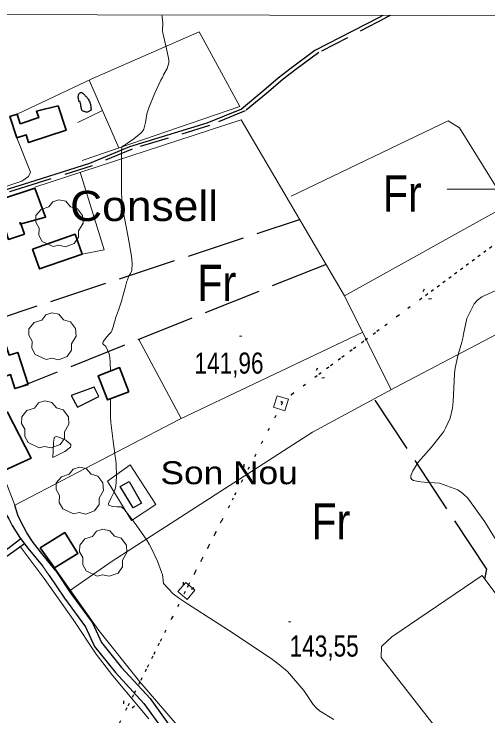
# Model space of a CAD drawing. Extents: x 483855 to 488461, y 4388206 to 4391419.
# Drawn here: x 484295.6 to 484491.9, y 4390781.6 to 4391072.6 of the extents above; entities that cross this region are included whole.
import ezdxf
from ezdxf.enums import TextEntityAlignment as Align

# ---------------------------------------------------------------- set-up
doc = ezdxf.new("R2010")
doc.units = 0
doc.header["$LTSCALE"] = 4
for name, pattern in [('DOTTED', [1.5, 0.3, -1.2]), ('LONG_DASHED', [7.5, 6, -1.5]), ('MEDIUM_DASHED', [4.5, 3, -1.5])]:
    doc.linetypes.add(name, pattern=pattern)
for name, color, linetype, lineweight in [('1', 7, 'Continuous', 13), ('21', 7, 'Continuous', 25), ('25', 7, 'LONG_DASHED', 25), ('29', 7, 'Continuous', 13), ('36', 7, 'Continuous', 25), ('38', 7, 'Continuous', 25), ('43', 7, 'DOTTED', 25), ('47', 7, 'Continuous', 35), ('51', 7, 'Continuous', 13), ('7', 7, 'Continuous', 13), ('9', 7, 'Continuous', 13)]:
    doc.layers.add(name, color=color, linetype=linetype, lineweight=lineweight)
doc.layers.add('31', color=7, linetype='Continuous')
doc.layers.add('5', color=7, linetype='Continuous')

msp = doc.modelspace()

# ---------------------------------------------------------------- linework, layer by layer
at = {"layer": '1'}
msp.add_line((484475, 4391000), (484525, 4391000), dxfattribs=at)
msp.add_lwpolyline([(484115.5, 4391072.6), (487689.7, 4391065.7), (487685.8, 4388753.5), (484110.5, 4388760.3)], close=True, dxfattribs=at)
at = {"layer": '21'}
for points in [[(484328.8, 4390917.84), (484319.29, 4390914.38), (484321.9, 4390909.66), (484330.8, 4390913.99)], [(484343.25, 4390878.75), (484348.42, 4390869.82), (484344.96, 4390867.88), (484339.52, 4390876.75)]]:
    msp.add_lwpolyline(points, close=True, dxfattribs=at)
msp.add_spline([(484322.66, 4391036.12), (484322.26, 4391037.5), (484322.23, 4391038.35), (484322.32, 4391038.99), (484323, 4391039.94), (484323.27, 4391040), (484323.85, 4391039.97), (484324.17, 4391039.77), (484324.66, 4391039.16), (484325.61, 4391038.28), (484326.28, 4391037.34), (484326.77, 4391036.47), (484327.12, 4391035.48), (484327.39, 4391034.11), (484327.39, 4391034.04), (484327.4, 4391032.68), (484327.33, 4391032.61), (484327.26, 4391032.55), (484326.53, 4391032.12), (484326, 4391031.95), (484325.42, 4391031.91), (484324.77, 4391032.13), (484324.2, 4391032.35), (484323.76, 4391032.69), (484323.58, 4391033.15), (484323.46, 4391033.55), (484323.36, 4391034.07), (484323.26, 4391035.05), (484323.04, 4391035.97), (484322.87, 4391036.5)], degree=3, dxfattribs=at)
at = {"layer": '25'}
for p, q in [((484282.36, 4390944.05), (484413.92, 4390987.45)), ((484424.89, 4390968.79), (484299.04, 4390918.32))]:
    msp.add_line(p, q, dxfattribs=at)
msp.add_lwpolyline([(484490.58, 4390838.33), (484491.44, 4390842.4), (484444.89, 4390913.1)], dxfattribs=at)
at = {"layer": '29'}
for points in [[(484311.84, 4390976.2), (484307.3, 4390978.32), (484305.89, 4390980.86), (484305.99, 4390983.84), (484304.62, 4390986.25), (484304.66, 4390989), (484306.82, 4390991.6), (484310.01, 4390992.6), (484311.66, 4390994.79), (484314.23, 4390995.62), (484317.09, 4390994.97), (484319.04, 4390992.7), (484321.85, 4390991.88), (484323.98, 4390989.03), (484324.22, 4390985.9), (484322.34, 4390982.75), (484322.34, 4390980.07), (484320.52, 4390977.46), (484316.9, 4390976.12), (484314.13, 4390976.75)], [(484308.93, 4390929.34), (484304.39, 4390931.46), (484302.98, 4390934), (484303.08, 4390936.98), (484301.71, 4390939.39), (484301.75, 4390942.14), (484303.91, 4390944.74), (484307.1, 4390945.74), (484308.75, 4390947.93), (484311.32, 4390948.76), (484314.18, 4390948.11), (484316.13, 4390945.84), (484318.94, 4390945.02), (484321.07, 4390942.17), (484321.31, 4390939.04), (484319.43, 4390935.89), (484319.43, 4390933.21), (484317.61, 4390930.6), (484313.99, 4390929.26), (484311.22, 4390929.89)], [(484305.98, 4390892.82), (484301.44, 4390894.94), (484300.03, 4390897.48), (484300.13, 4390900.46), (484298.76, 4390902.87), (484298.8, 4390905.62), (484300.96, 4390908.22), (484304.15, 4390909.22), (484305.8, 4390911.41), (484308.37, 4390912.24), (484311.23, 4390911.59), (484313.18, 4390909.32), (484315.99, 4390908.5), (484318.12, 4390905.65), (484318.36, 4390902.52), (484316.48, 4390899.37), (484316.48, 4390896.69), (484314.66, 4390894.08), (484311.04, 4390892.74), (484308.27, 4390893.37)], [(484320.31, 4390865.38), (484315.77, 4390867.5), (484314.36, 4390870.04), (484314.46, 4390873.02), (484313.09, 4390875.43), (484313.13, 4390878.18), (484315.29, 4390880.78), (484318.48, 4390881.78), (484320.13, 4390883.97), (484322.7, 4390884.8), (484325.56, 4390884.15), (484327.51, 4390881.88), (484330.32, 4390881.06), (484332.45, 4390878.21), (484332.69, 4390875.08), (484330.81, 4390871.93), (484330.81, 4390869.25), (484328.99, 4390866.64), (484325.37, 4390865.3), (484322.6, 4390865.93)], [(484330.01, 4390839.61), (484325.47, 4390841.73), (484324.06, 4390844.27), (484324.16, 4390847.25), (484322.79, 4390849.66), (484322.83, 4390852.41), (484324.99, 4390855.01), (484328.18, 4390856.01), (484329.83, 4390858.2), (484332.4, 4390859.03), (484335.26, 4390858.38), (484337.21, 4390856.11), (484340.02, 4390855.29), (484342.15, 4390852.44), (484342.39, 4390849.31), (484340.51, 4390846.16), (484340.51, 4390843.48), (484338.69, 4390840.87), (484335.07, 4390839.53), (484332.3, 4390840.16)]]:
    msp.add_lwpolyline(points, close=True, dxfattribs=at)
at = {"layer": '36'}
for points in [[(484286.4, 4390874.18), (484293.5, 4390863.28), (484294.88, 4390860.55), (484297.89, 4390855.67), (484301.36, 4390851.1), (484304.67, 4390847.22), (484307.34, 4390843.83)], [(484312.91, 4390841.73), (484307.08, 4390848.89), (484303.52, 4390853.55), (484300.94, 4390857.58), (484298.26, 4390862.47), (484297.16, 4390864.86), (484295.95, 4390869.05)], [(484312.91, 4390841.73), (484319.2, 4390832.42), (484328.08, 4390820.21), (484331.81, 4390812.11), (484340.13, 4390801.73), (484351.99, 4390788.86), (484361.05, 4390776.3)], [(484310.16, 4390839.87), (484316.48, 4390830.51), (484325.2, 4390818.52), (484328.96, 4390810.35), (484337.61, 4390799.57), (484349.41, 4390786.75), (484358.5, 4390774.16)]]:
    msp.add_lwpolyline(points, dxfattribs=at)
at = {"layer": '38'}
msp.add_line((484448.39, 4391071.96), (484446.6, 4391071.03), dxfattribs=at)
msp.add_line((484448.39, 4391071.96), (484446.6, 4391071.03), dxfattribs=at)
for points in [[(484446.6, 4391071.03), (484420.26, 4391057.4), (484410.47, 4391050.18), (484405.1, 4391046.04), (484399.1, 4391040.81), (484389.82, 4391033.18), (484375.53, 4391027.31), (484343.45, 4391017.59), (484326.91, 4391010.64), (484304.24, 4391003.47), (484269.98, 4390992.8), (484247.23, 4390986.88)], [(484298.38, 4390855.03), (484284.66, 4390844.48), (484263.45, 4390827.61), (484250.72, 4390819.35), (484232.48, 4390806.42), (484219.57, 4390795.92), (484207.6, 4390785.54), (484197.08, 4390777.65), (484194.16, 4390775.6), (484191.43, 4390772.82), (484188.02, 4390770.33), (484185.14, 4390766.66)]]:
    msp.add_lwpolyline(points, dxfattribs=at)
at = {"layer": '38', "linetype": 'MEDIUM_DASHED'}
for points in [[(484449.68, 4391071.02), (484421.9, 4391056.65), (484412.32, 4391049.58), (484407.04, 4391045.51), (484401.08, 4391040.31), (484391.43, 4391032.38), (484376.62, 4391026.3), (484344.55, 4391016.58), (484328.03, 4391009.64), (484305.23, 4391002.42), (484270.89, 4390991.73), (484248.08, 4390985.8)], [(484451.41, 4391071.95), (484450.1, 4391071.24), (484449.68, 4391071.02)], [(484451.41, 4391071.95), (484450.1, 4391071.24), (484449.68, 4391071.02)], [(484299.91, 4390853), (484285.88, 4390842.88), (484264.62, 4390825.98), (484251.84, 4390817.69), (484233.7, 4390804.82), (484220.86, 4390794.38), (484208.86, 4390783.98), (484198.26, 4390776.03), (484195.47, 4390774.06), (484192.74, 4390771.29), (484189.43, 4390768.87), (484186.7, 4390765.4), (484184, 4390762.15)]]:
    msp.add_lwpolyline(points, dxfattribs=at)
at = {"layer": '43'}
for p, q in [((484623.79, 4391072.48), (484406.1, 4390911.48)), ((484491.13, 4390974.37), (484462.99, 4390953.55)), ((484465.52, 4390958.54), (484462.99, 4390953.55)), ((484468.5, 4390954.52), (484462.99, 4390953.55)), ((484455.35, 4390947.91), (484454.55, 4390947.31)), ((484446.91, 4390941.66), (484418.77, 4390920.85)), ((484421.3, 4390925.83), (484418.77, 4390920.85)), ((484424.28, 4390921.81), (484418.77, 4390920.85)), ((484411.13, 4390915.2), (484410.33, 4390914.61)), ((484406.76, 4390911.49), (484390.76, 4390880.36)), ((484390.82, 4390885.95), (484390.76, 4390880.36)), ((484395.27, 4390883.67), (484390.76, 4390880.36)), ((484386.42, 4390871.91), (484385.96, 4390871.02)), ((484365.68, 4390837.04), (484365.61, 4390831.45)), ((484370.12, 4390834.75), (484365.61, 4390831.45)), ((484361.38, 4390822.94), (484360.93, 4390822.05)), ((484356.68, 4390813.55), (484341.01, 4390782.26)), ((484341.01, 4390787.85), (484341.01, 4390782.26)), ((484345.48, 4390785.61), (484341.01, 4390782.26))]:
    msp.add_line(p, q, dxfattribs=at)
at = {"layer": '43', "linetype": 'Continuous', "lineweight": 13}
for points in [[(484403.07, 4390909.6), (484404.58, 4390914.37), (484409.35, 4390912.86), (484407.84, 4390908.09)], [(484363.48, 4390833.17), (484366.74, 4390836.97), (484370.54, 4390833.71), (484367.28, 4390829.91)]]:
    msp.add_lwpolyline(points, close=True, dxfattribs=at)
at = {"layer": '43'}
for points in [[(484406.76, 4390911.49), (484366.53, 4390833.23), (484252.54, 4390605.6)], [(484381.61, 4390862.57), (484366.53, 4390833.23), (484365.63, 4390831.44)]]:
    msp.add_lwpolyline(points, dxfattribs=at)
at = {"layer": '47'}
for points in [[(484313.87, 4391034.52), (484317.24, 4391024.43), (484301.67, 4391019.25), (484300.57, 4391022.55), (484296.75, 4391021.29), (484293.83, 4391030.11), (484296.85, 4391031.12), (484298.18, 4391027.11), (484305.85, 4391029.67), (484304.96, 4391032.32)], [(484304.25, 4391000.42), (484248.07, 4390981.84), (484249.24, 4390978.3), (484253.59, 4390979.76), (484258.19, 4390966.02), (484255.93, 4390965.28), (484259.35, 4390954.81), (484279.44, 4390961.38), (484277.71, 4390966.66), (484269.15, 4390963.85), (484267.29, 4390969.49), (484265.4, 4390968.89), (484263.11, 4390976.06), (484289.54, 4390984.51), (484290.47, 4390981.57), (484292.32, 4390982.18), (484293.31, 4390979.15), (484299.89, 4390981.33), (484298.31, 4390986.08), (484297.95, 4390985.96), (484298.09, 4390985.52), (484308.65, 4390988.4)], [(484303.31, 4390975.14), (484320.93, 4390981.28), (484323.78, 4390973.09), (484306.16, 4390966.95)], [(484278.12, 4390958.71), (484261.12, 4390953.34), (484290.31, 4390882.75), (484302.64, 4390888.43), (484292.92, 4390907.57), (484289.89, 4390906.45), (484284.03, 4390919.43), (484294.08, 4390923.13), (484295.91, 4390917.32), (484301.4, 4390919.07), (484297.16, 4390932.34), (484293.55, 4390931.18), (484291.91, 4390936.27), (484282.99, 4390933.41), (484279.84, 4390943.23), (484282.36, 4390944.05), (484280.08, 4390951.03), (484270.04, 4390947.77), (484268.88, 4390951.31), (484278.06, 4390954.32), (484277.67, 4390955.5), (484279.24, 4390956.03)], [(484343.17, 4390915.97), (484339.33, 4390926.03), (484330.49, 4390922.65), (484334.33, 4390912.59)], [(484306.38, 4390851.33), (484316.71, 4390857.64), (484322.02, 4390848.93), (484312.37, 4390843.05)]]:
    msp.add_lwpolyline(points, close=True, dxfattribs=at)
at = {"layer": '51'}
for p, q in [((484327.87, 4391045.64), (484296.85, 4391031.12)), ((484326.77, 4391045.13), (484339.04, 4391017.08)), ((484332.27, 4391032.56), (484322.06, 4391027.62)), ((484323.77, 4391011.87), (484389.18, 4391034.19)), ((484389.64, 4391028.72), (484304.2, 4391000.87)), ((484432.52, 4390955.8), (484451.84, 4390916.86)), ((484347.31, 4390937.68), (484364.86, 4390904.91)), ((484336.23, 4390845.75), (484318.95, 4390833.78)), ((484310.16, 4390839.87), (484307.34, 4390843.83))]:
    msp.add_line(p, q, dxfattribs=at)
for points in [[(484389.18, 4391034.19), (484372.32, 4391065.22), (484327.87, 4391045.64)], [(484619.76, 4391060.63), (484500.57, 4390993.64), (484432.52, 4390955.8), (484389.64, 4391028.72)], [(484410.47, 4390997.02), (484475.45, 4391028.26), (484480.11, 4391025.41), (484499.98, 4390993.31)], [(484296.75, 4391021.29), (484302.37, 4391007.06), (484301.58, 4391005.27), (484298.9, 4391003.3), (484271.13, 4390993.99), (484251.8, 4390988.78), (484249.51, 4390988.55), (484247.7, 4390988.81), (484246.42, 4390989.38), (484245.41, 4390990.21), (484244.17, 4390991.82), (484238.95, 4391006.48)], [(484322.94, 4391006.98), (484332.9, 4390974.87), (484323.78, 4390973.09)], [(484601.7, 4390995.54), (484453.73, 4390917.88), (484419.26, 4390899.22), (484336.23, 4390845.75)], [(484290.59, 4390882.88), (484295.95, 4390869.05), (484364.32, 4390904.65), (484440.04, 4390940.66)], [(484298.13, 4390851.81), (484308.12, 4390838.57), (484320.05, 4390821.59), (484329.59, 4390807.23), (484336.53, 4390798.3), (484351.51, 4390780.49)], [(484478.11, 4390639.7), (484451.1, 4390679.45), (484441.26, 4390694.15), (484434.68, 4390703.55), (484429.37, 4390711.41), (484422.4, 4390719.56), (484413.25, 4390729.74), (484405.75, 4390737.04), (484394.27, 4390748.6), (484380.61, 4390759.62), (484365.75, 4390774.77), (484347.67, 4390795.75), (484330.72, 4390817.1), (484312.38, 4390843.06)], [(484484.36, 4390758.84), (484447.76, 4390805.87), (484447.83, 4390810.45), (484452.18, 4390814.35), (484489.49, 4390839.77), (484589.78, 4390705.66)]]:
    msp.add_lwpolyline(points, dxfattribs=at)
msp.add_lwpolyline([(484334.34, 4390878.91), (484343.66, 4390885.76), (484354.39, 4390869.26), (484344.23, 4390862.63)], close=True, dxfattribs=at)
at = {"layer": '7'}
for p, q in [((484388.98, 4390939), (484389.98, 4390939)), ((484409.28, 4390820.59), (484410.28, 4390820.59))]:
    msp.add_line(p, q, dxfattribs=at)
at = {"layer": '9'}
for points in [[(484357.04, 4391071.2), (484357.22, 4391068.92), (484357.16, 4391065.74), (484357.29, 4391064.68), (484357.47, 4391063.54), (484358.62, 4391058.8), (484359.63, 4391054.25), (484359.72, 4391053.24), (484359.74, 4391052.34), (484359.1, 4391049.97), (484357.59, 4391047.36), (484357.05, 4391046.3), (484356.45, 4391045.1)], [(484357.04, 4391071.2), (484356.99, 4391071.85), (484356.88, 4391072.13)], [(484356.45, 4391045.1), (484353.86, 4391039.54), (484351.5, 4391033.75), (484351.04, 4391032.4), (484350.68, 4391031.16), (484350.11, 4391027.6), (484349.37, 4391024.83), (484348.9, 4391024.09), (484348.32, 4391023.36), (484345.28, 4391020.82), (484342.21, 4391018.8), (484341.61, 4391018.4), (484341.12, 4391018.08), (484340.27, 4391017.47), (484340.17, 4391015.69), (484340.15, 4391014.62), (484340.14, 4391013.31), (484340.12, 4391006.49), (484340.16, 4390999.43), (484340.17, 4390997.96), (484340.2, 4390996.7), (484340.31, 4390993.91), (484340.78, 4390990.93), (484341.03, 4390989.56), (484341.33, 4390987.94), (484342.85, 4390980.11), (484344.23, 4390972.27), (484344.44, 4390970.66), (484344.58, 4390969.28), (484344.47, 4390966.31), (484343.92, 4390965.08), (484343.78, 4390964.81), (484343.65, 4390964.56), (484343.21, 4390963.91), (484342.73, 4390962.87), (484342.56, 4390962.38), (484342.38, 4390961.81), (484341.62, 4390959.01), (484340.68, 4390955.56), (484340.39, 4390954.57), (484340.08, 4390953.57), (484338.84, 4390949.84), (484337.7, 4390946.46), (484337.46, 4390945.67), (484337.24, 4390944.95), (484336.74, 4390942.91), (484336.09, 4390941.24), (484335.8, 4390940.76), (484335.45, 4390940.27), (484333.76, 4390938.43), (484332.5, 4390936.72), (484332.42, 4390936.31), (484332.46, 4390935.93), (484333.59, 4390934.79), (484335.04, 4390931.77), (484335.29, 4390930.2), (484335.47, 4390928.31), (484335.51, 4390924.57)], [(484497.95, 4390959.23), (484489.38, 4390955.28), (484487.63, 4390953.93), (484486.17, 4390952.48), (484483.15, 4390946.3), (484481.86, 4390939.82), (484481.49, 4390938.18), (484481.11, 4390936.6), (484479.67, 4390931.42), (484478.47, 4390926.4), (484478.24, 4390924.92), (484478.06, 4390923.4), (484477.78, 4390917.57), (484477.56, 4390911.94), (484477.42, 4390910.54), (484477.25, 4390909.21), (484476.33, 4390904.99), (484474.41, 4390900.86), (484473.61, 4390899.59), (484472.69, 4390898.25), (484468.37, 4390892.95), (484464.12, 4390888.01), (484463.23, 4390886.89), (484462.48, 4390885.89), (484460.81, 4390883.2), (484460.17, 4390881.54), (484460.06, 4390881.19), (484459.98, 4390880.9), (484459.96, 4390880.22), (484460.22, 4390879.85), (484460.33, 4390879.74), (484460.46, 4390879.64), (484461.03, 4390879.24), (484463.1, 4390878.82), (484464.17, 4390878.7), (484465.46, 4390878.58), (484471.88, 4390878.1), (484479.53, 4390875.35), (484481.58, 4390873.79), (484483.61, 4390871.89), (484490.7, 4390862.14), (484496.84, 4390851.96)], [(484335.54, 4390913.05), (484335.52, 4390908.26), (484335.61, 4390905.66), (484335.74, 4390903.2), (484336.61, 4390895.52), (484337.54, 4390889.18), (484337.72, 4390887.57), (484337.86, 4390886.03), (484338.1, 4390880.99), (484337.75, 4390876.76), (484337.52, 4390875.74), (484337.24, 4390874.78), (484335.76, 4390871.82), (484334.73, 4390869.75), (484334.73, 4390869.35), (484334.86, 4390869.02), (484336.36, 4390868.42), (484338.33, 4390868.34), (484338.75, 4390868.32), (484339.12, 4390868.32), (484340.01, 4390868.33), (484341.33, 4390867.15), (484341.97, 4390866.39), (484342.74, 4390865.44), (484346.5, 4390860.45), (484350.59, 4390854.42), (484351.55, 4390852.82), (484352.44, 4390851.25), (484355.06, 4390845.83), (484356.76, 4390841.22), (484357.06, 4390840.16), (484357.3, 4390839.19), (484357.58, 4390836.48), (484361.58, 4390832.25), (484364.18, 4390830.32), (484367.41, 4390828.07), (484384.44, 4390817.22), (484402.14, 4390805.49), (484405.79, 4390802.68), (484408.9, 4390800.07), (484415.63, 4390792.23), (484419.49, 4390786.38), (484420.8, 4390785.01), (484422.2, 4390783.75)], [(484422.2, 4390783.75), (484428.13, 4390780.14)]]:
    msp.add_lwpolyline(points, dxfattribs=at)
msp.add_lwpolyline([(484311.72, 4390888.75), (484316.63, 4390891.18), (484319.03, 4390893.07), (484319.19, 4390893.58), (484319.12, 4390894.1), (484317.02, 4390895.93), (484314.13, 4390897.2), (484313.56, 4390897.36), (484313.09, 4390897.43), (484312.24, 4390896.99), (484312.07, 4390895.66), (484312.02, 4390895.17), (484311.98, 4390894.63)], close=True, dxfattribs=at)

# ---------------------------------------------------------------- texts
at = {"layer": '31', "width": 0.85}
for p in [(484456.47, 4390990.65), (484379.61, 4390953.61), (484426.87, 4390854.76)]:
    msp.add_text('Fr', height=15, dxfattribs=at).set_placement(p, align=Align.CENTER)
at = {"layer": '5', "width": 1.1}
msp.add_text('Consell', height=12.5, dxfattribs=at).set_placement((484318.83, 4390986.77))
at = {"layer": '5', "width": 1.15}
msp.add_text('Son Nou', height=9.5, dxfattribs=at).set_placement((484413.14, 4390877.68), align=Align.RIGHT)
at = {"layer": '7', "width": 0.8}
for s, p in [('141,96', (484370.34, 4390923.51)), ('143,55', (484409.78, 4390806.22))]:
    msp.add_text(s, height=8.75, dxfattribs=at).set_placement(p)

doc.saveas('drawing.dxf')
